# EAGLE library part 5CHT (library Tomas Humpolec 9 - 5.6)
FILTER 5CHT 400~520MHz SMD helical filter Features Compact low-profile helical filters for surface mounting, ideal for mobile communications equipment. RoHS compliant Applications Surface mounting type: Cellular, cordless telephones, paging devices, etc.
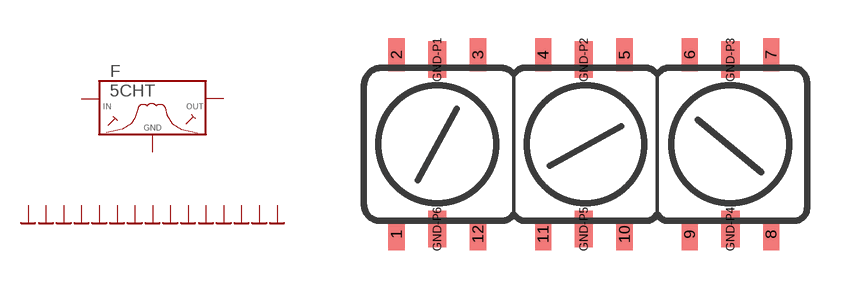
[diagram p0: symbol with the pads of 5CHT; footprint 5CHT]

Designator prefix F

## 5CHT5HCT-SMD  [5CHT]
1  1-IN  pas
2  GND-2  pwr
3  GND-3  pwr
4  GND-4  pwr
5  GND-5  pwr
6  GND-6  pwr
7  7-OUT  pas
8  GND-8  pwr
9  GND-9  pwr
10  GND-10  pwr
11  GND-11  pwr
12  GND-12  pwr
GND-P1  GND-P1  pwr
GND-P2  GND-P2  pwr
GND-P3  GND-P3  pwr
GND-P4  GND-P4  pwr
GND-P5  GND-P5  pwr
GND-P6  GND-P6  pwr

## Footprint 5CHT (pad centres in mm)
SMD HELICAL FILTER 5CHT for Surface Mounting 400 - 520MHz 6 x 17.3 x 6.3 mm
smd 0.635 x 1.27: 1 -6.985,4.572; 2 -6.985,11.557; 3 -3.81,11.557; 4 -1.27,11.557; 5 1.905,11.557; 6 4.445,11.557; 7 7.62,11.557; 8 7.62,4.572; 9 4.445,4.572; 10 1.905,4.572; 11 -1.27,4.572; 12 -3.81,4.572
smd 0.711 x 1.422: GND-P1 -5.397,11.367; GND-P2 0.318,11.367; GND-P3 6.032,11.367; GND-P4 6.032,4.763; GND-P5 0.318,4.763; GND-P6 -5.397,4.763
